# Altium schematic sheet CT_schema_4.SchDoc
size 390 x 355 mm
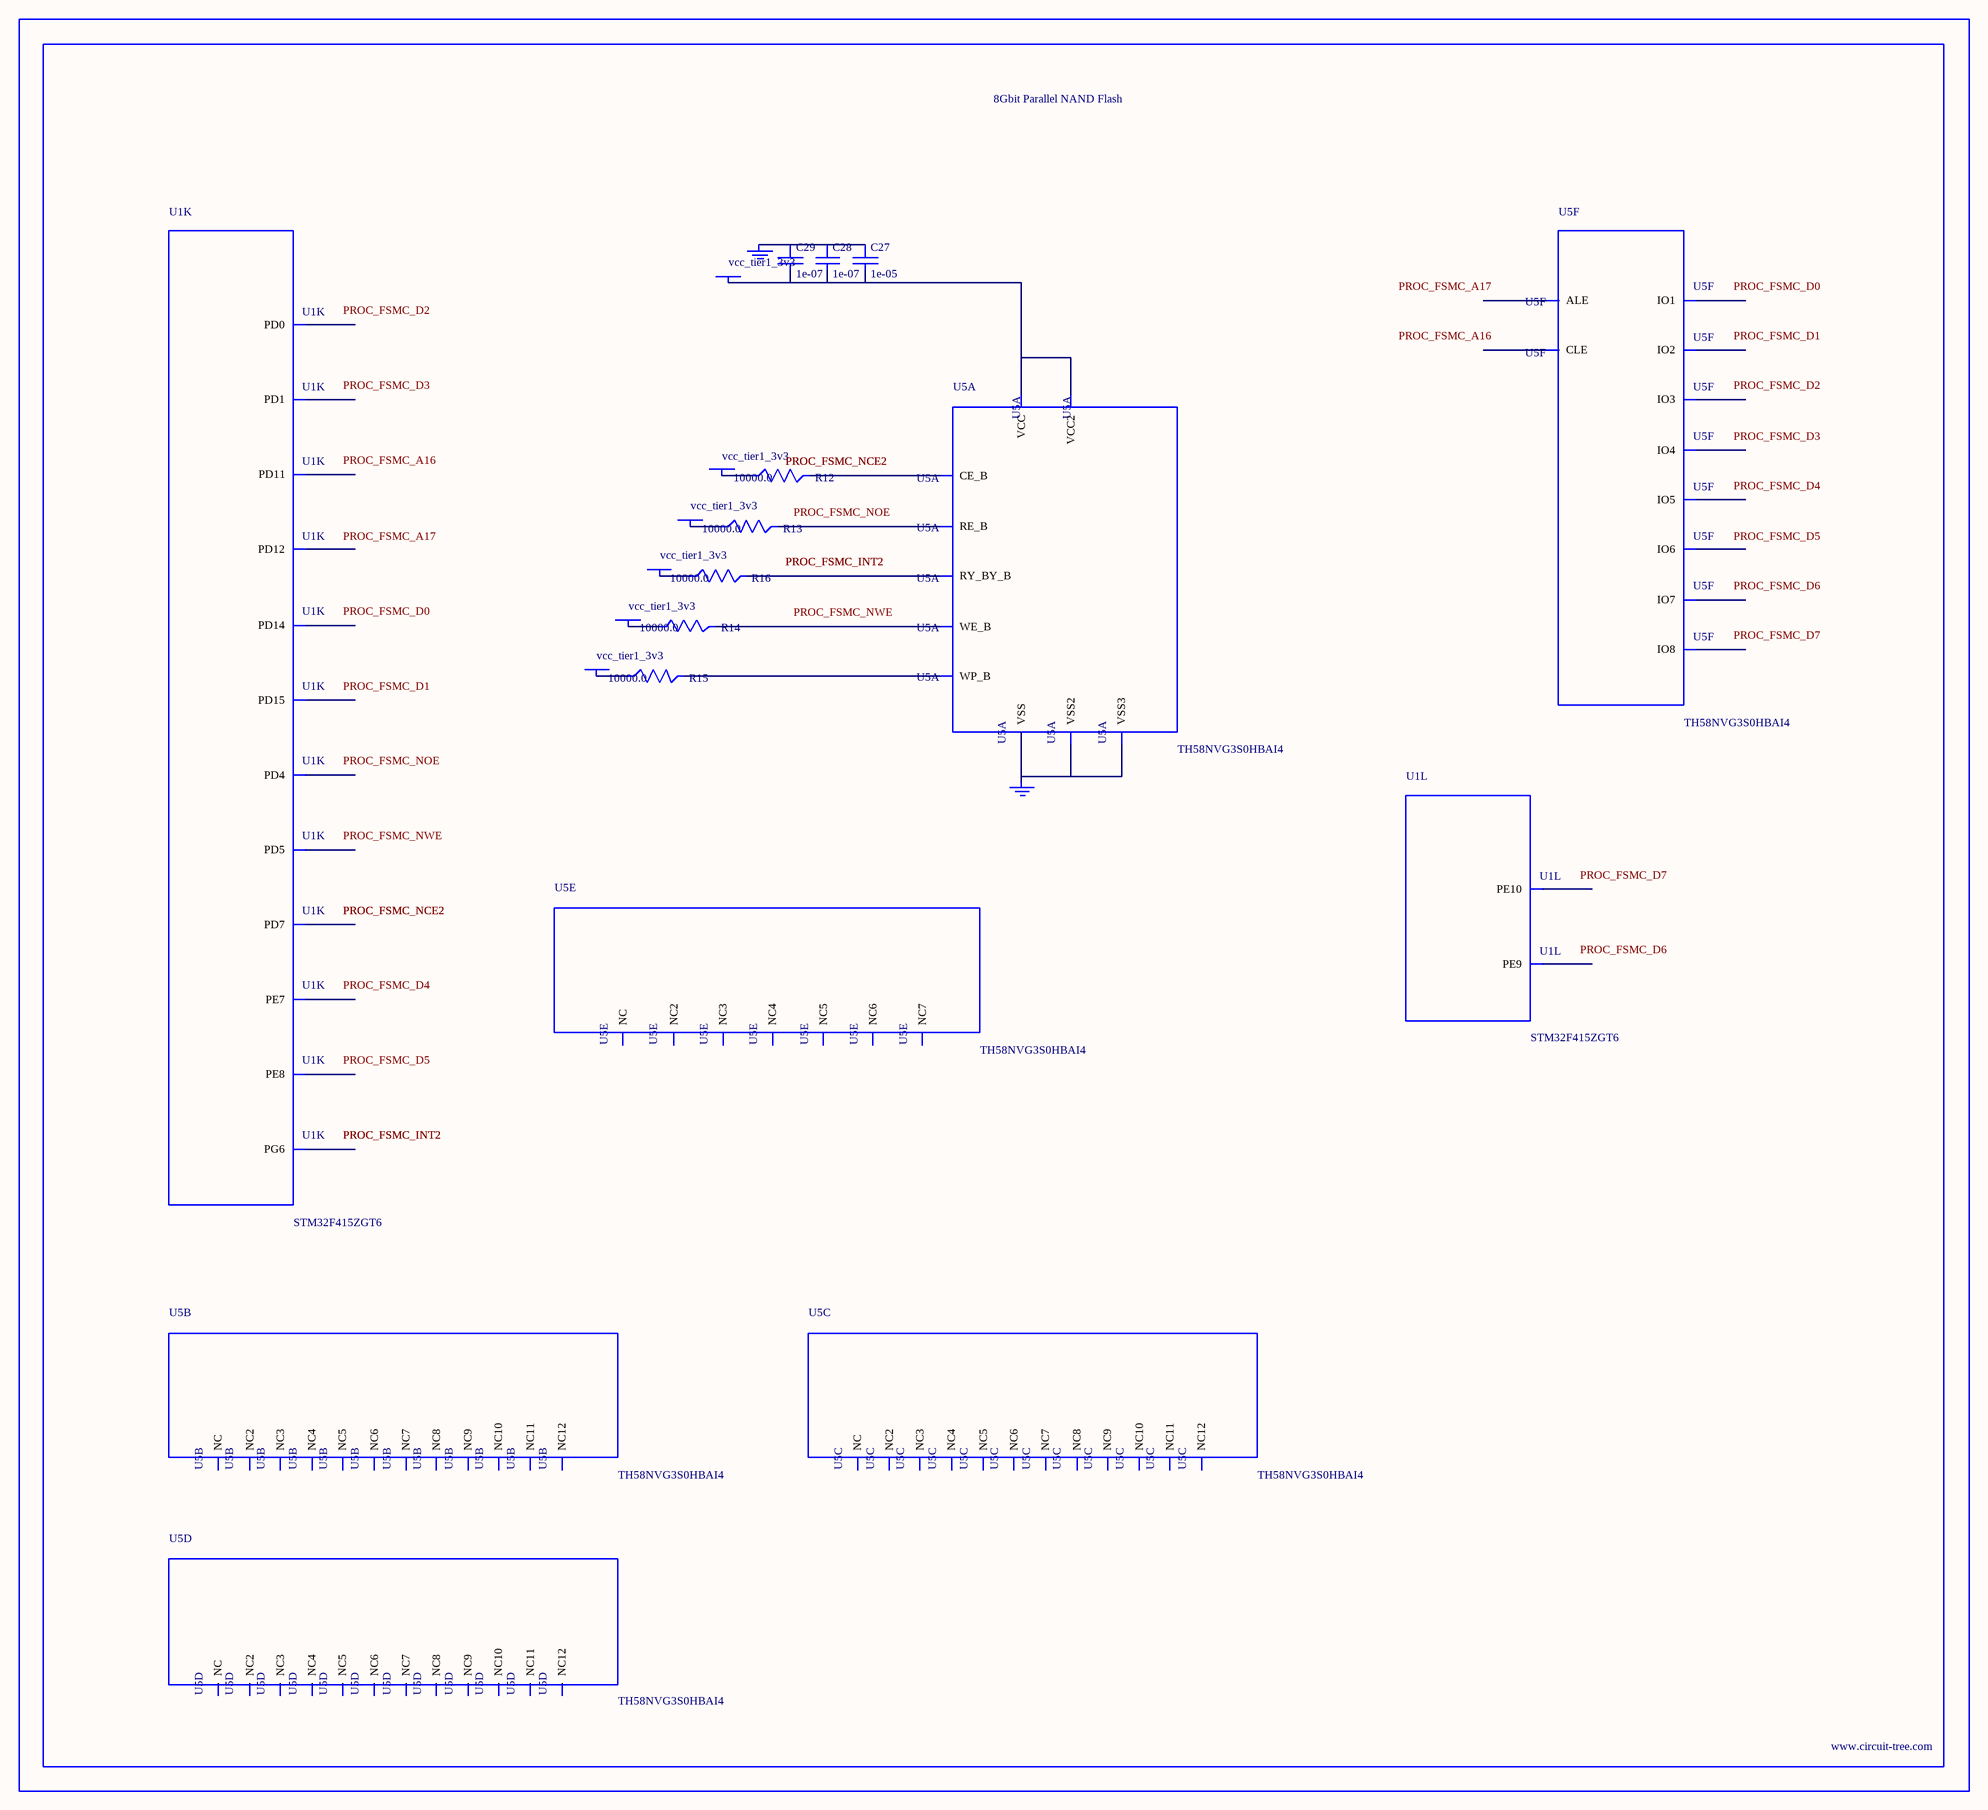
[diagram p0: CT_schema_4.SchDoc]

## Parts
BORDER3  (no value)
C27  1e-05  [C0805]
C28  1e-07  [C0402]
C29  1e-07  [C0402]
GND_INSTANCE_3_0  (no value)
GND_INSTANCE_3_1  (no value)
POWER_INSTANCE_3_0  vcc_tier1_3v3
POWER_INSTANCE_3_1  vcc_tier1_3v3
POWER_INSTANCE_3_2  vcc_tier1_3v3
POWER_INSTANCE_3_3  vcc_tier1_3v3
POWER_INSTANCE_3_4  vcc_tier1_3v3
POWER_INSTANCE_3_5  vcc_tier1_3v3
R12  10000.0  [R0603]
R13  10000.0  [R0603]
R14  10000.0  [R0603]
R15  10000.0  [R0603]
R16  10000.0  [R0603]
U1  STM32F415ZGT6  [LQFP144]  (parts K,L of 12)
U5  TH58NVG3S0HBAI4  [TH58NVG3S0HBAI4]  (parts A,B,C,D,E,F of 6)

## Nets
NetC27_1: C27.1 C28.1 C29.1 GND_INSTANCE_3_0.0(GND)
NetC27_2: C27.2 C28.2 C29.2 POWER_INSTANCE_3_5.0(PWR) U5.H8(VCC) U5.J6(VCC2)
NetGND_INSTANCE_3_1_0: GND_INSTANCE_3_1.0(GND) U5.C5(VSS) U5.K3(VSS2) U5.K8(VSS3)
NetPOWER_INSTANCE_3_0_0: POWER_INSTANCE_3_0.0(PWR) R12.1
NetPOWER_INSTANCE_3_1_0: POWER_INSTANCE_3_1.0(PWR) R13.1
NetPOWER_INSTANCE_3_2_0: POWER_INSTANCE_3_2.0(PWR) R14.1
NetPOWER_INSTANCE_3_3_0: POWER_INSTANCE_3_3.0(PWR) R15.1
NetPOWER_INSTANCE_3_4_0: POWER_INSTANCE_3_4.0(PWR) R16.1
NetR12_2: R12.2 U5.C6(CE_B)
NetR13_2: R13.2 U5.D4(RE_B)
NetR14_2: R14.2 U5.C7(WE_B)
NetR15_2: R15.2 U5.C3(WP_B)
NetR16_2: R16.2 U5.C8(RY_BY_B)

Not connected (* = marked no-connect by the designer): U1 58(PE7) 59(PE8) 60(PE9) 63(PE10) 80(PD11) 81(PD12) 85(PD14) 86(PD15) 91(PG6) 114(PD0) 115(PD1) 118(PD4) 119(PD5) 123(PD7); U5 A1(NC) A2(NC3) A9(NC4) A10(NC2) B1(NC5) B9(NC7) B10(NC6) C4(ALE) D3(NC8) D5(CLE) D6(NC9) D7(NC10) D8(NC11) E3(NC12) E4(NC) E5(NC2) E6(NC3) E7(NC4) E8(NC5) F3(NC6) F4(NC7) F5(NC8) F6(NC9) F7(NC10) F8(NC11) G3(NC12) G4(NC) G5(NC2) G6(NC3) G7(NC4) G8(NC5) H3(NC6) H4(IO1) H5(NC7) H6(NC8) H7(NC9) J3(NC10) J4(IO2) J5(NC11) J7(IO6) J8(IO8) K4(IO3) K5(IO4) K6(IO5) K7(IO7) L1(NC12) L2(NC2) L9(NC3) L10(NC) M1(NC4) M2(NC6) M9(NC7) M10(NC5)

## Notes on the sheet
- Labels drawn without touching a wire or pin: PROC_FSMC_A16, PROC_FSMC_A17, PROC_FSMC_D0, PROC_FSMC_D1, PROC_FSMC_D2, PROC_FSMC_D3, PROC_FSMC_D4, PROC_FSMC_D5, PROC_FSMC_D6, PROC_FSMC_D7, PROC_FSMC_NOE, PROC_FSMC_NWE

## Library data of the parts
BORDER3 = BORDER_PAGE3
C27 = C0805C106K8RACTU
C28 C29 = C0402C104K3RACTU
GND_INSTANCE_3_0 GND_INSTANCE_3_1 = GND
POWER_INSTANCE_3_0-POWER_INSTANCE_3_5 = PWR
R12-R16 = RC0603JR-0710KL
